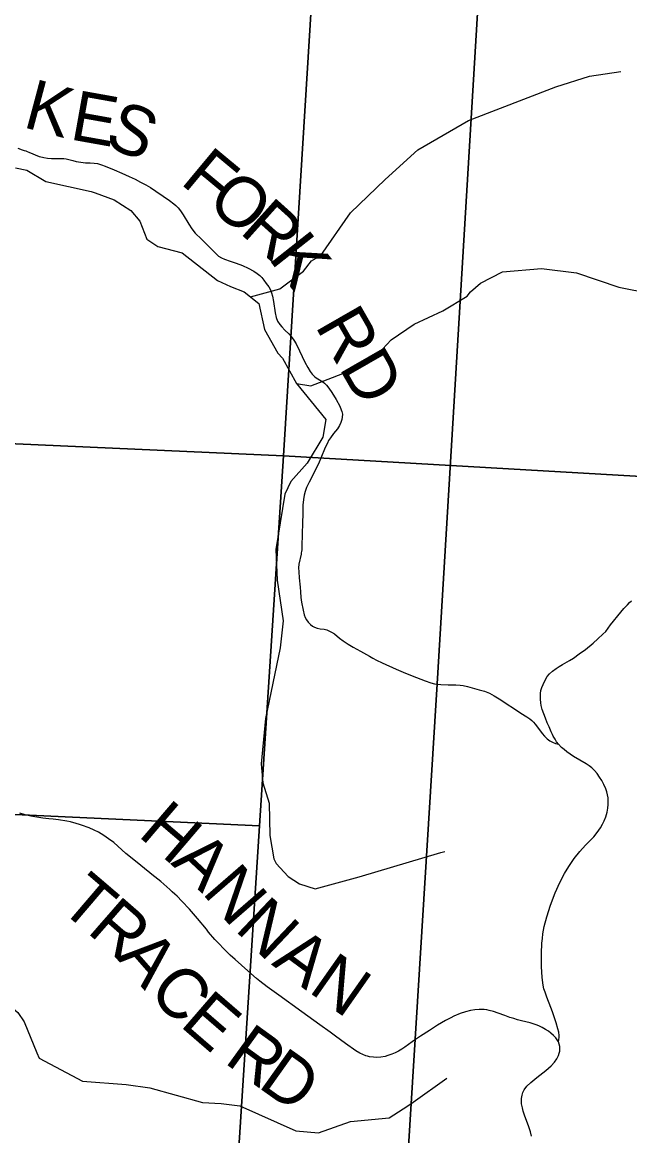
# Model space of a CAD drawing. Extents: x 0 to 34, y 0 to 22.
# Drawn here: x 27.996 to 28.686, y 17.66 to 18.925 of the extents above; entities that cross this region are included whole.
import ezdxf

# ---------------------------------------------------------------- set-up
doc = ezdxf.new("R2010")
doc.units = 0
for name, color, linetype in [('GM_X_County_Road', 7, 'Continuous'), ('GM_X_County_Road_Text', 7, 'Continuous'), ('GM_X_County_Text', 7, 'Continuous'), ('GM_X_Minor_River', 7, 'Continuous'), ('GM_X_Section', 7, 'Continuous')]:
    doc.layers.add(name, color=color, linetype=linetype)

msp = doc.modelspace()

# ---------------------------------------------------------------- linework, layer by layer
at = {"layer": 'GM_X_County_Road'}
for points in [[(27.9913, 18.7817), (27.9964, 18.7799), (27.9986, 18.7791), (28.0003, 18.7786), (28.0019, 18.7779), (28.0036, 18.7774), (28.0157, 18.7725), (28.0192, 18.7714), (28.0209, 18.771), (28.0251, 18.7703), (28.0294, 18.7701), (28.0393, 18.7702), (28.0436, 18.77), (28.0461, 18.7697), (28.0491, 18.7689), (28.0539, 18.7678), (28.0576, 18.7668), (28.0629, 18.7659), (28.068, 18.7653), (28.0736, 18.765), (28.0779, 18.7646), (28.0816, 18.7642), (28.0864, 18.7629), (28.0905, 18.7615), (28.1007, 18.757), (28.1093, 18.7534), (28.1178, 18.7496), (28.1245, 18.7464), (28.1306, 18.7433), (28.1366, 18.7401), (28.142, 18.737), (28.1482, 18.7329), (28.1563, 18.7271), (28.1635, 18.7223), (28.1684, 18.7186), (28.1707, 18.7167), (28.1733, 18.714), (28.176, 18.7107), (28.1791, 18.706), (28.1854, 18.6953), (28.1889, 18.6902), (28.1929, 18.6854), (28.1998, 18.6783), (28.2165, 18.6616), (28.2194, 18.6592), (28.2225, 18.6572), (28.2259, 18.6556), (28.2323, 18.6534), (28.2394, 18.6511), (28.2464, 18.6484), (28.2531, 18.6453), (28.2592, 18.6421), (28.2633, 18.6394), (28.2662, 18.6371), (28.2685, 18.6349), (28.2707, 18.6319), (28.2735, 18.6282), (28.2764, 18.6241), (28.2782, 18.6208), (28.2795, 18.6174), (28.2805, 18.6138), (28.2816, 18.6077), (28.2836, 18.5948), (28.2848, 18.5893), (28.2864, 18.5853), (28.2887, 18.5816), (28.291, 18.5788), (28.2945, 18.5752), (28.299, 18.5709), (28.3019, 18.5677), (28.3048, 18.5637), (28.3074, 18.5594), (28.3112, 18.5516), (28.3172, 18.5387), (28.3205, 18.5327), (28.3234, 18.5279), (28.3257, 18.525), (28.3284, 18.5224), (28.3303, 18.5208), (28.3339, 18.5185), (28.3377, 18.5163), (28.3396, 18.5148), (28.3418, 18.5126), (28.3445, 18.5092), (28.348, 18.5041), (28.3528, 18.4961), (28.357, 18.4885), (28.3587, 18.4845), (28.3593, 18.4828), (28.3599, 18.4797), (28.3598, 18.476), (28.3593, 18.4736), (28.3581, 18.4701), (28.3565, 18.4668), (28.3542, 18.463), (28.35, 18.4576), (28.3463, 18.4527), (28.3443, 18.4496), (28.3429, 18.4468), (28.3405, 18.4418), (28.3356, 18.4297), (28.3336, 18.4252), (28.3291, 18.4156), (28.3223, 18.4023), (28.3192, 18.3962), (28.3175, 18.3916), (28.3164, 18.3874), (28.3156, 18.3825), (28.3151, 18.3763), (28.3149, 18.3658), (28.3147, 18.3566), (28.3143, 18.3429), (28.314, 18.3299), (28.3137, 18.3256), (28.3134, 18.3237), (28.3131, 18.3219), (28.313, 18.3207), (28.3104, 18.3092), (28.3101, 18.3049), (28.3103, 18.3004), (28.3108, 18.2936), (28.3118, 18.2832), (28.3122, 18.2777), (28.3127, 18.2713), (28.3134, 18.266), (28.3152, 18.2569), (28.3166, 18.2515), (28.3177, 18.2486), (28.3191, 18.2458), (28.321, 18.2433), (28.3236, 18.2406), (28.326, 18.2387), (28.3282, 18.2375), (28.3311, 18.2365), (28.3347, 18.2358), (28.3391, 18.2352), (28.3421, 18.2344), (28.3444, 18.2336), (28.3477, 18.232), (28.3508, 18.2299), (28.3566, 18.2253), (28.361, 18.2219), (28.3641, 18.2199), (28.3666, 18.2184), (28.3723, 18.215), (28.3806, 18.2102), (28.3907, 18.2045), (28.3944, 18.2024), (28.3987, 18.2002), (28.4053, 18.197), (28.4209, 18.1898), (28.4316, 18.1853), (28.4443, 18.1804), (28.454, 18.1766), (28.4603, 18.1743), (28.4645, 18.1732), (28.4679, 18.1727)], [(28.5986, 18.1158), (28.5971, 18.1188), (28.5947, 18.1242), (28.5926, 18.129), (28.5905, 18.1342), (28.5887, 18.1392), (28.587, 18.1442), (28.5858, 18.1486), (28.5852, 18.1517), (28.5849, 18.1559), (28.5849, 18.1593), (28.5851, 18.1623), (28.5855, 18.1656), (28.5866, 18.1692), (28.5878, 18.1723), (28.5901, 18.1774), (28.5927, 18.1815), (28.5951, 18.1845), (28.5985, 18.1875), (28.6028, 18.1907), (28.6062, 18.1931), (28.61, 18.1953), (28.6178, 18.1998), (28.6223, 18.2025), (28.629, 18.2073), (28.6359, 18.2123), (28.6448, 18.2196), (28.6501, 18.2243), (28.6558, 18.2296), (28.6591, 18.2327), (28.6646, 18.2403), (28.6763, 18.2547), (28.6795, 18.2588), (28.6836, 18.2628), (28.6862, 18.2655), (28.6883, 18.2677)], [(28.4679, 18.1727), (28.4717, 18.1724), (28.4802, 18.1722), (28.4887, 18.1721), (28.4936, 18.1718), (28.4973, 18.1712), (28.5021, 18.1702), (28.5153, 18.1666), (28.5212, 18.1648), (28.5269, 18.1625), (28.5324, 18.1596), (28.5398, 18.1551), (28.5471, 18.1503), (28.5544, 18.1456), (28.5628, 18.14), (28.5694, 18.1359), (28.5728, 18.1334), (28.5751, 18.1314), (28.5771, 18.1295), (28.5789, 18.1274), (28.5827, 18.1225), (28.5868, 18.117), (28.5896, 18.1138), (28.5927, 18.1108), (28.5957, 18.1086), (28.5986, 18.1069), (28.602, 18.1056), (28.6055, 18.1047)], [(28.6054, 17.7665), (28.6059, 17.7689), (28.6063, 17.7717), (28.6062, 17.7739), (28.6057, 17.7774), (28.6048, 17.7812), (28.6026, 17.7882), (28.5985, 17.8006), (28.5966, 17.8055), (28.5921, 17.8172), (28.5901, 17.8228), (28.5889, 17.8269), (28.5881, 17.8308), (28.5869, 17.8397), (28.5862, 17.8522), (28.5861, 17.8668), (28.5866, 17.8785), (28.5871, 17.8841), (28.5877, 17.8891), (28.5892, 17.8977), (28.5922, 17.9087), (28.5962, 17.9217), (28.6018, 17.9359), (28.6069, 17.9477), (28.6122, 17.9577), (28.6171, 17.9659), (28.6232, 17.9748), (28.6298, 17.9829), (28.6362, 17.9899), (28.6456, 17.9996), (28.6495, 18.0043), (28.6532, 18.0097), (28.6554, 18.0137), (28.6572, 18.0175), (28.6593, 18.0223), (28.6606, 18.0274), (28.6613, 18.0319), (28.6617, 18.0363), (28.6618, 18.0403), (28.6617, 18.0437), (28.6612, 18.0472), (28.6604, 18.0505), (28.6592, 18.0541), (28.657, 18.0588), (28.6546, 18.0635), (28.6521, 18.0673), (28.6494, 18.0712), (28.6464, 18.0747), (28.6431, 18.0778), (28.6401, 18.08), (28.6367, 18.0822), (28.6298, 18.0864), (28.6225, 18.0908), (28.615, 18.0959), (28.6117, 18.0985), (28.6089, 18.101), (28.6055, 18.1047), (28.6033, 18.1075), (28.6015, 18.1104), (28.5995, 18.1138), (28.5986, 18.1158)], [(28.4429, 17.769), (28.4392, 17.7664), (28.4308, 17.7606), (28.4275, 17.7583), (28.4237, 17.7561), (28.4198, 17.754), (28.4161, 17.7526), (28.4116, 17.7509), (28.4085, 17.75), (28.4035, 17.7492), (28.3991, 17.7489), (28.3953, 17.749), (28.3909, 17.7496), (28.3884, 17.7501), (28.3865, 17.7507), (28.383, 17.7521), (28.3796, 17.7537), (28.3752, 17.7564), (28.3636, 17.7647), (28.352, 17.773), (28.346, 17.7774), (28.3345, 17.7857), (28.3138, 17.8007), (28.2876, 17.8194), (28.2745, 17.8289), (28.2661, 17.8354), (28.2622, 17.8385), (28.2524, 17.8471), (28.2381, 17.8601), (28.2326, 17.8651), (28.225, 17.8725), (28.2199, 17.8777), (28.2151, 17.8829), (28.208, 17.8913), (28.2054, 17.8946), (28.1954, 17.9065), (28.1861, 17.9173), (28.1777, 17.9264), (28.1721, 17.932), (28.1698, 17.9341), (28.1667, 17.9371), (28.1639, 17.9396), (28.1538, 17.9486), (28.147, 17.9541), (28.1436, 17.9567), (28.1412, 17.9586), (28.1249, 17.9718), (28.1141, 17.9805), (28.1002, 17.9928), (28.0944, 17.9973), (28.0888, 18.0011), (28.0829, 18.0046), (28.078, 18.0071), (28.0724, 18.0095), (28.0689, 18.0109), (28.0672, 18.0115), (28.0646, 18.0124), (28.0614, 18.0134), (28.0576, 18.0145), (28.051, 18.0163), (28.0471, 18.0171), (28.0374, 18.0187), (28.0313, 18.0194), (28.0264, 18.02), (28.0197, 18.0208), (28.0062, 18.023), (27.9996, 18.0245), (27.9936, 18.0263)], [(28.5746, 17.6592), (28.5736, 17.6642), (28.5717, 17.6699), (28.5668, 17.6833), (28.5654, 17.6876), (28.5644, 17.6915), (28.5635, 17.696), (28.5632, 17.6995), (28.5634, 17.7023), (28.564, 17.7059), (28.5649, 17.7089), (28.5664, 17.712), (28.5694, 17.716), (28.5738, 17.7205), (28.5807, 17.7259), (28.5911, 17.7338), (28.5971, 17.7391), (28.6008, 17.7433), (28.6036, 17.7473), (28.6054, 17.7511), (28.6063, 17.7535), (28.6068, 17.7561), (28.6071, 17.7586), (28.6068, 17.7612), (28.6063, 17.764), (28.6054, 17.7665), (28.6039, 17.7689), (28.6022, 17.7709), (28.5996, 17.7738), (28.5968, 17.7764), (28.5939, 17.7786), (28.5907, 17.7807), (28.587, 17.7829), (28.5832, 17.7847), (28.5802, 17.786), (28.5768, 17.7871), (28.5731, 17.7882), (28.5684, 17.7893), (28.5634, 17.7905), (28.5588, 17.7917), (28.5548, 17.7929), (28.5501, 17.7943), (28.5443, 17.7964), (28.5367, 17.7992), (28.5315, 17.801), (28.5268, 17.8023), (28.5239, 17.8028), (28.5208, 17.8031), (28.5182, 17.8033), (28.5153, 17.8033), (28.5104, 17.8029), (28.5056, 17.8021), (28.4997, 17.8006), (28.4938, 17.7987), (28.4865, 17.7955), (28.4832, 17.7939), (28.4772, 17.7909), (28.4681, 17.7855), (28.4644, 17.7832), (28.4587, 17.7795), (28.4488, 17.7731), (28.4429, 17.769)]]:
    msp.add_lwpolyline(points, dxfattribs=at)
at = {"layer": 'GM_X_County_Text'}
for points in [[(28.4159, 17.3358), (28.4427, 17.7695), (28.4677, 18.1732), (28.5249, 19.1245), (28.5443, 19.4375), (28.5808, 20.0106), (28.6062, 20.4055), (27.8401, 20.4449), (27.0539, 20.4845), (26.781, 20.4973), (26.0533, 20.5337), (24.4417, 20.6174), (23.8372, 20.6485), (23.8372, 14.4177)], [(29.547, 20.3639), (28.6062, 20.4055), (28.5808, 20.0106), (28.5443, 19.4375), (28.5249, 19.1245), (28.4677, 18.1732), (28.4427, 17.7695), (28.4159, 17.3358)]]:
    msp.add_lwpolyline(points, dxfattribs=at)
at = {"layer": 'GM_X_Minor_River'}
for points in [[(28.2555, 18.613), (28.2888, 18.6218), (28.3156, 18.6421), (28.3247, 18.6539), (28.3356, 18.66), (28.3691, 18.7084), (28.4084, 18.7462), (28.4457, 18.7798), (28.5032, 18.8131), (28.6024, 18.8516), (28.6407, 18.8635), (28.6763, 18.869)], [(27.9885, 18.7594), (28.0017, 18.7567), (28.0232, 18.7439), (28.0746, 18.7324), (28.0791, 18.7311), (28.1008, 18.7232), (28.1197, 18.7108), (28.1299, 18.6987), (28.138, 18.6783), (28.1502, 18.67), (28.178, 18.663), (28.2182, 18.6313), (28.2328, 18.6248), (28.2485, 18.6186), (28.2651, 18.6055), (28.2714, 18.5757), (28.2868, 18.549), (28.2919, 18.5432), (28.3077, 18.5146), (28.3412, 18.4736), (28.3376, 18.4533), (28.32, 18.4238), (28.3013, 18.4032), (28.2944, 18.3886), (28.2842, 18.3259), (28.2858, 18.2909), (28.2927, 18.2447), (28.2891, 18.2141), (28.2727, 18.1337), (28.2677, 18.0822), (28.2697, 18.0609), (28.2766, 18.0375), (28.2777, 18.0011), (28.2822, 17.9743), (28.2847, 17.9693), (28.2982, 17.9545), (28.3112, 17.9461), (28.3292, 17.9402), (28.3791, 17.9538), (28.4718, 17.9816), (28.4764, 17.9826)], [(28.3079, 18.5143), (28.3242, 18.5118), (28.3801, 18.5335), (28.4056, 18.5536), (28.4154, 18.5639), (28.4413, 18.5817), (28.4739, 18.597), (28.5016, 18.6136), (28.5055, 18.6187), (28.5168, 18.6283), (28.5417, 18.6411), (28.5861, 18.645), (28.626, 18.6403), (28.6739, 18.624), (28.7103, 18.6168)], [(27.8455, 17.8815), (27.8518, 17.8784), (27.8794, 17.879), (27.8995, 17.8677), (27.9119, 17.854), (27.9543, 17.8314), (27.9912, 17.7999), (27.9984, 17.7894), (28.0128, 17.754), (28.0157, 17.7478), (28.0648, 17.722), (28.1145, 17.7181), (28.1413, 17.7142), (28.2012, 17.6975), (28.2224, 17.6964), (28.2435, 17.6938), (28.3072, 17.6656), (28.3329, 17.6633), (28.3692, 17.6762), (28.4131, 17.6801), (28.4343, 17.6938), (28.4405, 17.6978), (28.4784, 17.7251)]]:
    msp.add_lwpolyline(points, dxfattribs=at)
at = {"layer": 'GM_X_Section'}
for points in [[(27.3196, 19.501), (28.356, 19.4486), (28.293, 18.4323), (27.254, 18.479)], [(28.356, 19.4486), (29.4164, 19.4097), (29.3481, 18.3713), (28.293, 18.4323)], [(27.254, 18.479), (28.293, 18.4323), (28.2659, 18.0119), (27.228, 18.0601)], [(29.3481, 18.3713), (29.2849, 17.3606), (28.2266, 17.4004), (28.2269, 17.4056), (28.2386, 17.5871), (28.2659, 18.0119), (28.293, 18.4323)], [(28.2659, 18.0119), (28.2386, 17.5871), (27.2029, 17.6387), (27.228, 18.0601)]]:
    msp.add_lwpolyline(points, close=True, dxfattribs=at)

# ---------------------------------------------------------------- texts
at = {"layer": 'GM_X_County_Road_Text'}
for s, height, rotation, p in [('K', 0.0568, 345.0795, (27.9957, 18.806)), ('E', 0.0568, 349.8639, (28.0491, 18.792)), ('S', 0.0568, 337.7336, (28.0879, 18.7854)), ('F', 0.0568, 320.2334, (28.1745, 18.7423)), ('O', 0.0568, 320.2299, (28.204, 18.7178)), ('R', 0.0568, 318.0746, (28.242, 18.6862)), ('K', 0.0568, 308.2394, (28.2749, 18.6569)), ('RD', 0.05682, 299.8686, (28.3282, 18.5802)), ('H', 0.0568, 319.4556, (28.1266, 18.0011)), ('A', 0.0568, 316.9297, (28.1641, 17.9691)), ('N', 0.0568, 310.932, (28.1995, 17.9361)), ('T', 0.0568, 319.5063, (28.0364, 17.919)), ('R', 0.0568, 318.886, (28.0686, 17.8915)), ('N', 0.0568, 316.5339, (28.2365, 17.8939)), ('A', 0.0568, 323.4664, (28.2785, 17.8547)), ('A', 0.0568, 311.2869, (28.1023, 17.8622)), ('N', 0.0568, 324.9857, (28.32, 17.824)), ('C', 0.0568, 314.4447, (28.1377, 17.8221)), ('E', 0.0568, 319.17, (28.1741, 17.7853)), ('R', 0.0568, 324.1743, (28.2244, 17.7435)), ('D', 0.0568, 324.6199, (28.2626, 17.7159))]:
    msp.add_text(s, height=height, rotation=rotation, dxfattribs=at).set_placement(p)

doc.saveas('drawing.dxf')
